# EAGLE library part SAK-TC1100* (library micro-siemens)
32-bit Consumer Class TriCore Single-Chip Microcontroller Source: http://www.infineon.com/cmc_upload/documents/010/9915/TC1100_umsu_v10.pdf
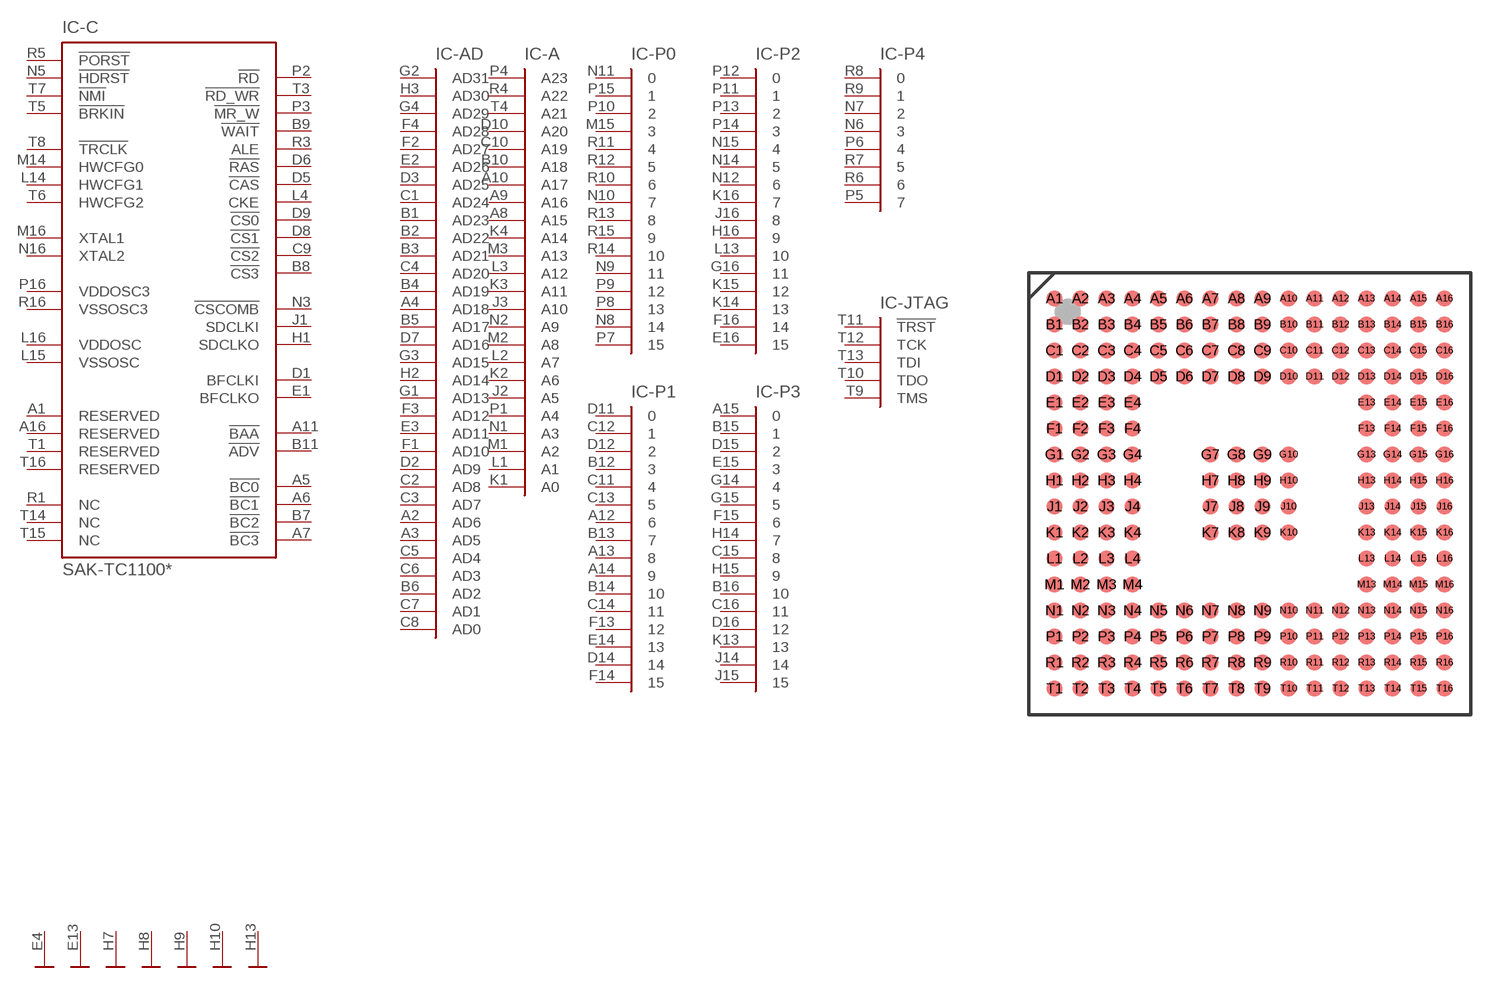
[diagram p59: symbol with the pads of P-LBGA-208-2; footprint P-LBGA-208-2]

Designator prefix IC; gates -C=TC1100 -P0=PORT16 -P1=PORT16 -P2=PORT16 -P3=PORT16 -P4=PORT8 -AD=AD31 -A=A23 -JTAG=JTAG -VSS1=VSS -VSS2=VSS -VSS3=VSS -VSS4=VSS -VSS5=VSS -VSS6=VSS -VSS7=VSS -VSS8=VSS -VSS9=VSS -VSS10=VSS -VSS11=VSS -VSS12=VSS -VSS13=VSS -VSS14=VSS -VSS15=VSS -VSS16=VSS -VDD1=VDD -VDD2=VDD -VDD3=VDD -VDD4=VDD -VDD5=VDD -VDD6=VDD -VDD7=VDD -VDD8=VDD -VDD9=VDD -VDDP1=VDDP -VDDP2=VDDP -VDDP3=VDDP -VDDP4=VDDP -VDDP5=VDDP -VDDP6=VDDP

## SAK-TC1100 (OC_FARNELL: unknown; OC_NEWARK: unknown)  [P-LBGA-208-2]
A1  -C:RESERVED  pas
A2  -AD:AD6
A3  -AD:AD5
A4  -AD:AD18
A5  -C:!BC0
A6  -C:!BC1
A7  -C:!BC3
A8  -A:A15  out
A9  -A:A16  out
A10  -A:A17  out
A11  -C:!BAA  out
A12  -P1:6  in
A13  -P1:8  in
A14  -P1:9  in
A15  -P3:0  in
A16  -C:RESERVED  pas
B1  -AD:AD23
B2  -AD:AD22
B3  -AD:AD21
B4  -AD:AD19
B5  -AD:AD17
B6  -AD:AD2
B7  -C:!BC2
B8  -C:!CS3  out
B9  -C:!WAIT  in
B10  -A:A18  out
B11  -C:!ADV  out
B12  -P1:3  in
B13  -P1:7  in
B14  -P1:10  in
B15  -P3:1  in
B16  -P3:10  in
C1  -AD:AD24
C2  -AD:AD8
C3  -AD:AD7
C4  -AD:AD20
C5  -AD:AD4
C6  -AD:AD3
C7  -AD:AD1
C8  -AD:AD0
C9  -C:!CS2  out
C10  -A:A19  out
C11  -P1:4  in
C12  -P1:1  in
C13  -P1:5  in
C14  -P1:11  in
C15  -P3:8  in
C16  -P3:11  in
D1  -C:BFCLKI  in
D2  -AD:AD9
D3  -AD:AD25
D4  -VDDP1:VDDP  pwr
D5  -C:!CAS  out
D6  -C:!RAS  out
D7  -AD:AD16
D8  -C:!CS1  out
D9  -C:!CS0  out
D10  -A:A20  out
D11  -P1:0  in
D12  -P1:2  in
D13  -VDDP2:VDDP  pwr
D14  -P1:14  in
D15  -P3:2  in
D16  -P3:12  in
E1  -C:BFCLKO  out
E2  -AD:AD26
E3  -AD:AD11
E4  -VSS1:VSS  pwr
E13  -VSS2:VSS  pwr
E14  -P1:13  in
E15  -P3:3  in
E16  -P2:15  in
F1  -AD:AD10
F2  -AD:AD27
F3  -AD:AD12
F4  -AD:AD28
F13  -P1:12  in
F14  -P1:15  in
F15  -P3:6  in
F16  -P2:14  in
G1  -AD:AD13
G2  -AD:AD31
G3  -AD:AD15
G4  -AD:AD29
G7  -VDD1:VDD  pwr
G8  -VDD2:VDD  pwr
G9  -VDD3:VDD  pwr
G10  -VDD4:VDD  pwr
G13  -VDD5:VDD  pwr
G14  -P3:4  in
G15  -P3:5  in
G16  -P2:11  in
H1  -C:SDCLKO  out
H2  -AD:AD14
H3  -AD:AD30
H4  -VDDP3:VDDP  pwr
H7  -VSS3:VSS  pwr
H8  -VSS4:VSS  pwr
H9  -VSS5:VSS  pwr
H10  -VSS6:VSS  pwr
H13  -VSS7:VSS  pwr
H14  -P3:7  in
H15  -P3:9  in
H16  -P2:9  in
J1  -C:SDCLKI  in
J2  -A:A5  out
J3  -A:A10  out
J4  -VSS8:VSS  pwr
J7  -VSS9:VSS  pwr
J8  -VSS10:VSS  pwr
J9  -VSS11:VSS  pwr
J10  -VSS12:VSS  pwr
J13  -VDDP4:VDDP  pwr
J14  -P3:14  in
J15  -P3:15  in
J16  -P2:8  in
K1  -A:A0  out
K2  -A:A6  out
K3  -A:A11  out
K4  -A:A14  out
K7  -VDD6:VDD  pwr
K8  -VDD7:VDD  pwr
K9  -VDD8:VDD  pwr
K10  -VDD9:VDD  pwr
K13  -P3:13  in
K14  -P2:13  in
K15  -P2:12  in
K16  -P2:7  in
L1  -A:A1  out
L2  -A:A7  out
L3  -A:A12  out
L4  -C:CKE  out
L13  -P2:10  in
L14  -C:HWCFG1  in
L15  -C:VSSOSC  in
L16  -C:VDDOSC  in
M1  -A:A2  out
M2  -A:A8  out
M3  -A:A13  out
M4  -VDDP5:VDDP  pwr
M13  -VSS13:VSS  pwr
M14  -C:HWCFG0  in
M15  -P0:3  in
M16  -C:XTAL1  in
N1  -A:A3  out
N2  -A:A9  out
N3  -C:!CSCOMB  out
N4  -VSS14:VSS  pwr
N5  -C:!HDRST
N6  -P4:3  in
N7  -P4:2  in
N8  -P0:14  in
N9  -P0:11  in
N10  -P0:7  in
N11  -P0:0  in
N12  -P2:6  in
N13  -VDDP6:VDDP  pwr
N14  -P2:5  in
N15  -P2:4  in
N16  -C:XTAL2  out
P1  -A:A4  out
P2  -C:!RD  out
P3  -C:!MR_W  out
P4  -A:A23  out
P5  -P4:7  in
P6  -P4:4  in
P7  -P0:15  in
P8  -P0:13  in
P9  -P0:12  in
P10  -P0:2  in
P11  -P2:1  in
P12  -P2:0  in
P13  -P2:2  in
P14  -P2:3  in
P15  -P0:1  in
P16  -C:VDDOSC3  in
R1  -C:NC  pas
R2  -VSS15:VSS  pwr
R3  -C:ALE  out
R4  -A:A22  out
R5  -C:!PORST  in
R6  -P4:6  in
R7  -P4:5  in
R8  -P4:0  in
R9  -P4:1  in
R10  -P0:6  in
R11  -P0:4  in
R12  -P0:5  in
R13  -P0:8  in
R14  -P0:10  in
R15  -P0:9  in
R16  -C:VSSOSC3  in
T1  -C:RESERVED  pas
T2  -VSS16:VSS  pwr
T3  -C:!RD_WR  out
T4  -A:A21  out
T5  -C:!BRKIN  in
T6  -C:HWCFG2  in
T7  -C:!NMI  in
T8  -C:!TRCLK  out
T9  -JTAG:TMS  in
T10  -JTAG:TDO  out
T11  -JTAG:!TRST  in
T12  -JTAG:TCK  in
T13  -JTAG:TDI  in
T14  -C:NC  pas
T15  -C:NC  pas
T16  -C:RESERVED  pas

## Footprint P-LBGA-208-2 (pad centres in mm)
P-LBGA-208-2 Low Profile Plastic Ball Grid Array Package Source: http://www.infineon.com .. TC1130_DS_v031.pdf
smd 0.6 x 0.6: A1 -7.5,7.5; A2 -6.5,7.5; A3 -5.5,7.5; A4 -4.5,7.5; A5 -3.5,7.5; A6 -2.5,7.5; A7 -1.5,7.5; A8 -0.5,7.5; A9 0.5,7.5; A10 1.5,7.5; A11 2.5,7.5; A12 3.5,7.5; A13 4.5,7.5; A14 5.5,7.5; A15 6.5,7.5; A16 7.5,7.5; B1 -7.5,6.5; B2 -6.5,6.5; B3 -5.5,6.5; B4 -4.5,6.5; B5 -3.5,6.5; B6 -2.5,6.5; B7 -1.5,6.5; B8 -0.5,6.5; B9 0.5,6.5; B10 1.5,6.5; B11 2.5,6.5; B12 3.5,6.5; B13 4.5,6.5; B14 5.5,6.5; B15 6.5,6.5; B16 7.5,6.5; C1 -7.5,5.5; C2 -6.5,5.5; C3 -5.5,5.5; C4 -4.5,5.5; C5 -3.5,5.5; C6 -2.5,5.5; C7 -1.5,5.5; C8 -0.5,5.5; C9 0.5,5.5; C10 1.5,5.5; C11 2.5,5.5; C12 3.5,5.5; C13 4.5,5.5; C14 5.5,5.5; C15 6.5,5.5; C16 7.5,5.5; D1 -7.5,4.5; D2 -6.5,4.5; D3 -5.5,4.5; D4 -4.5,4.5; D5 -3.5,4.5; D6 -2.5,4.5; D7 -1.5,4.5; D8 -0.5,4.5; D9 0.5,4.5; D10 1.5,4.5; D11 2.5,4.5; D12 3.5,4.5; D13 4.5,4.5; D14 5.5,4.5; D15 6.5,4.5; D16 7.5,4.5; E1 -7.5,3.5; E2 -6.5,3.5; E3 -5.5,3.5; E4 -4.5,3.5; E13 4.5,3.5; E14 5.5,3.5; E15 6.5,3.5; E16 7.5,3.5; F1 -7.5,2.5; F2 -6.5,2.5; F3 -5.5,2.5; F4 -4.5,2.5; F13 4.5,2.5; F14 5.5,2.5; F15 6.5,2.5; F16 7.5,2.5; G1 -7.5,1.5; G2 -6.5,1.5; G3 -5.5,1.5; G4 -4.5,1.5; G7 -1.5,1.5; G8 -0.5,1.5; G9 0.5,1.5; G10 1.5,1.5; G13 4.5,1.5; G14 5.5,1.5; G15 6.5,1.5; G16 7.5,1.5; H1 -7.5,0.5; H2 -6.5,0.5; H3 -5.5,0.5; H4 -4.5,0.5; H7 -1.5,0.5; H8 -0.5,0.5; H9 0.5,0.5; H10 1.5,0.5; H13 4.5,0.5; H14 5.5,0.5; H15 6.5,0.5; H16 7.5,0.5; J1 -7.5,-0.5; J2 -6.5,-0.5; J3 -5.5,-0.5; J4 -4.5,-0.5; J7 -1.5,-0.5; J8 -0.5,-0.5; J9 0.5,-0.5; J10 1.5,-0.5; J13 4.5,-0.5; J14 5.5,-0.5; J15 6.5,-0.5; J16 7.5,-0.5; K1 -7.5,-1.5; K2 -6.5,-1.5; K3 -5.5,-1.5; K4 -4.5,-1.5; K7 -1.5,-1.5; K8 -0.5,-1.5; K9 0.5,-1.5; K10 1.5,-1.5; K13 4.5,-1.5; K14 5.5,-1.5; K15 6.5,-1.5; K16 7.5,-1.5; L1 -7.5,-2.5; L2 -6.5,-2.5; L3 -5.5,-2.5; L4 -4.5,-2.5; L13 4.5,-2.5; L14 5.5,-2.5; L15 6.5,-2.5; L16 7.5,-2.5; M1 -7.5,-3.5; M2 -6.5,-3.5; M3 -5.5,-3.5; M4 -4.5,-3.5; M13 4.5,-3.5; M14 5.5,-3.5; M15 6.5,-3.5; M16 7.5,-3.5; N1 -7.5,-4.5; N2 -6.5,-4.5; N3 -5.5,-4.5; N4 -4.5,-4.5; N5 -3.5,-4.5; N6 -2.5,-4.5; N7 -1.5,-4.5; N8 -0.5,-4.5; N9 0.5,-4.5; N10 1.5,-4.5; N11 2.5,-4.5; N12 3.5,-4.5; N13 4.5,-4.5; N14 5.5,-4.5; N15 6.5,-4.5; N16 7.5,-4.5; P1 -7.5,-5.5; P2 -6.5,-5.5; P3 -5.5,-5.5; P4 -4.5,-5.5; P5 -3.5,-5.5; P6 -2.5,-5.5; P7 -1.5,-5.5; P8 -0.5,-5.5; P9 0.5,-5.5; P10 1.5,-5.5; P11 2.5,-5.5; P12 3.5,-5.5; P13 4.5,-5.5; P14 5.5,-5.5; P15 6.5,-5.5; P16 7.5,-5.5; R1 -7.5,-6.5; R2 -6.5,-6.5; R3 -5.5,-6.5; R4 -4.5,-6.5; R5 -3.5,-6.5; R6 -2.5,-6.5; R7 -1.5,-6.5; R8 -0.5,-6.5; R9 0.5,-6.5; R10 1.5,-6.5; R11 2.5,-6.5; R12 3.5,-6.5; R13 4.5,-6.5; R14 5.5,-6.5; R15 6.5,-6.5; R16 7.5,-6.5; T1 -7.5,-7.5; T2 -6.5,-7.5; T3 -5.5,-7.5; T4 -4.5,-7.5; T5 -3.5,-7.5; T6 -2.5,-7.5; T7 -1.5,-7.5; T8 -0.5,-7.5; T9 0.5,-7.5; T10 1.5,-7.5; T11 2.5,-7.5; T12 3.5,-7.5; T13 4.5,-7.5; T14 5.5,-7.5; T15 6.5,-7.5; T16 7.5,-7.5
